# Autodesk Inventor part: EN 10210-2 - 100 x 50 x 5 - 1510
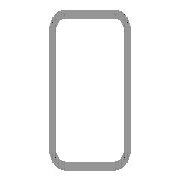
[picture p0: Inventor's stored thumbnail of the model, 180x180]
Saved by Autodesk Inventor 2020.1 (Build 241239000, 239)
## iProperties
Created: 2019-01
Part Number: EN 10210-2 - 100 x 50 x 5 - 1510
Material: Stahl, weich
Description: Rohrleitung
Document SubType Name: Modeling
Standard: DIN
Designer: lutzd
Standard Revision: 2006-07
Standards Organization: DIN
Language: de-DE
Size Designation: 100 x 50 x 5
Categories: <MemberInstance><Categories><Category DisplayName="Profile" InternalName="089c4875-fa83-4c05-b084-43b9cc11f5ed" Mnemonic="GRDR"><CategoryParameter DisplayName="
Stock Number: 100 x 50 x 5
Mass: 16276.9 g
Surface Area: 8159.41 cm^2
Volume: 2073.49 cm^3
Density: 7.85 g/cm^3
Appearance: Semi-Polished(8)
IsCustomPart: 1
_CCFamilyMember: 159
_CCFamilyDisplayName: DIN EN 10210-2 (USAS B17.1 rechteckig) - Rohrleitung — In Klammern angegebene Größen wurden aufgehoben
_FrameMemberDoc: Frame Member File
_Version: 15.0.0
_GetPNFromCC: 1
Title: Profil-Bauteil
Author: lutzd
Revision Number: -
G_W: 50,000 mm
G_H: 100,000 mm
+2FD8ED02-A42B-4087-B00B-C18EB6F43CBD+SCHNITTDETAIL1: Schnittwinkel 90,00 grd
+1027D788-42BA-481B-BA4D-CE2702A5B16C+SCHNITTDETAIL2: Schnittwinkel 90,00 grd
G_L: 1510,000 mm
DocNumber: ADSK-014253
Folder: .
Dimensions: 50x100x1510 mm
Mass: 16,277 kg
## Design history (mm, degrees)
node "Startebene"
node "Endebene"
sketch "Skizze"
  geometry: L1 (-25, -42.5)-(-25, 42.5); L2 (-17.5, 50)-(17.5, 50); L3 (25, 42.5)-(25, -42.5); L4 (17.5, -50)-(-17.5, -50); L5 (-15, 45)-(15, 45); L6 (20, 40)-(20, -40); L7 (15, -45)-(-15, -45); L8 (-20, -40)-(-20, 40); L9 (0, 72.175)-(0, -72.175) reference; L10 (-37.175, 0)-(37.175, 0) reference; A1 r 7.5 centre (-17.5, -42.5) between (-25, -42.5) and (-17.5, -50); A2 r 7.5 centre (-17.5, 42.5) between (-17.5, 50) and (-25, 42.5); A3 r 7.5 centre (17.5, 42.5) between (25, 42.5) and (17.5, 50); A4 r 7.5 centre (17.5, -42.5) between (17.5, -50) and (25, -42.5); A5 r 5 centre (-15, -40) between (-20, -40) and (-15, -45); A6 r 5 centre (-15, 40) between (-15, 45) and (-20, 40); A7 r 5 centre (15, 40) between (20, 40) and (15, 45); A8 r 5 centre (15, -40) between (15, -45) and (20, -40)
  constraints: 16 end point, 16 point on circle, 16 tangent, 8 centre point, 6 equal radius, 4 parallel, 2 perpendicular, 2 other
  dimensions: "d7" = 7.5 radius of A1 (= G_IR); "d10" = 100 distance between parallel lines of L2 L4 (= G_H); "d11" = 50 distance between parallel lines of L1 L3 (= G_W); "d12" = 5 distance between parallel lines of L3 L6 (= G_T); "d15" = 50 distance between parallel lines of L2 L10 (= 0.5 x d10); "d16" = 25 distance between parallel lines of L9 L3 (= 0.5 x d11); "d19" = 5 radius of A5 (= G_T); "d20" = 5 distance between parallel lines of L4 L7 (= G_T)
extrude "Körper" new body sketch "Skizze" stored distance "d3" = 1510 (= G_L); taper "d4" = 0 deg
node "Driven Length"
  sketch "Sketch3"
    geometry: L1 (0, 0)-(10, 0) reference
    constraints: 2 end point, 1 horizontal
  workplane "Work Plane3"
  sketch "Sketch4"
    geometry: L1 (-2, 25)-(12, 25) reference; L2 (-2, 1535)-(12, 1535) reference
    dimensions: "d18" = 1510 distance between parallel lines of L1 L2 (derived)
workplane "Arbeitsebene4"
feature "Trennen1"
workplane "Arbeitsebene5"
feature "Trennen2"
body "Solid1"
other parameters: "G_W" = 50 [user parameter; used in 1 equation term], "G_H" = 100 [user parameter; used in 1 equation term], "G_T" = 5 [user parameter; used in 3 equation terms], "G_IR" = 7.5 [user parameter; used in 1 equation term], "G_L" = 1510 (= d18) [user parameter; used in 1 equation term], "G_OFFSET_START" = -25 [user parameter; used in 1 equation term], "d13" = 25 (= -G_OFFSET_START), "d14" = 1535 (= G_OFFSET_END + B_L), "B_L" = 1585 [user parameter; used in 1 equation term], "d17" = 90 deg
